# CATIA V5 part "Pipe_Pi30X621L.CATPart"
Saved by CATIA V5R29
Part number: Pipe_Pi30X621L
Bounding box of the stored display mesh (mm): x -15 to 15, y -14.97 to 14.97, z -621 to 0
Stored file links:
  C:\Users\Administrator\Desktop\프로젝트\Boxfold\Pipe_Pi30X621L.CATPart
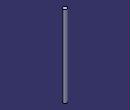
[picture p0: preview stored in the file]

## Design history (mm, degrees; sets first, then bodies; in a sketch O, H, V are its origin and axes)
Body1 (main body)
  Sketch1 on xy-plane, origin (0, 0, 0), H (1, 0, 0), V (0, 1, 0)
    circle A1 centre (0, 0) radius 15
    radius A1 = 15
  Pad1: profile Sketch1, direction (0, 0, -1), length 621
